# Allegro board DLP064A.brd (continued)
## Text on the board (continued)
User.30: FIGURE | SIZE | 10.0 | 12.0 | 40.0 | 63.0 | 135.0 | 66.93x35.43 | 106.3x35.43 | DRILL CHART: TOP to BOTTOM | ALL UNITS ARE IN MILS | TOLERANCE | +0.0/-10.0 | +3.0/-12.0 | +3.0/-3.0 | PLATED | NON-PLATED | QTY | 300 | 12 | 1 | 10 | 4 | 2
